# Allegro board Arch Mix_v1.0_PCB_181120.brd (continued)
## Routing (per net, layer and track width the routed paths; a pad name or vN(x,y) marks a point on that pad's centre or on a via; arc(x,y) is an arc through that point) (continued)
VDD_USB_3V: length 9.3
  TOP w0.254: U8.K8 v1(40.37,19.72)
  GND05 w0.305: v1(40.37,19.72) 41.72,19.72 42.38,20.37 42.7,20.37
  GND05 w0.381: 42.7,20.37 43.84,20.37 45.76,22.29 v2(46.37,22.29)
  BOTTOM w0.203: v1(40.37,19.72) 40.37,19.62 40.89,19.1 C59.1
  BOTTOM w0.305: C48.1 v2(46.37,22.29)
VDDA_1V1_CAP: length 2
  TOP w0.254: v1(42.34,16.36) 42.34,16.45 U8.P10
  BOTTOM w0.305: v1(42.34,16.36) 42.7,16.01 C52.1 42.7,15.12 C53.1
VDDA_2V5_CAP: length 2
  TOP w0.254: U8.P8 v1(41.02,16.47)
  BOTTOM w0.305: v1(41.02,16.47) 41.07,16.42 C61.1 C62.1
VDDA_ADC_3V3: length 5.7
  TOP w0.203: 45.01,17.1 44.66,17.44 U8.N14
  TOP w0.305: 45.01,17.1 45.16,16.94 47.22,16.94 C30.1 C29.1 C28.1 R30.2
BOOT_MODE[0]: length 17.1
  TOP w0.127: SW1.4 41.17,29.34 v2(40.44,30.08) 40.34,30.18 39.7,30.18 R19.2 ; U8.F11 v1(42.97,22.32)
  LYR03 w0.127: v2(40.44,30.08) 39.87,29.5 39.87,29.15 41.33,27.69 41.96,27.69 42.99,28.72 44.23,28.72 v2(44.65,29.14)
  BOTTOM w0.102: v1(42.97,22.32) 43.3,22.64 43.3,23.45 43.3,25.39 43.99,26.09 43.99,26.35
  BOTTOM w0.127: v2(44.65,29.14) 44.65,28.7 43.99,28.04 43.99,26.35
BOOT_MODE[1]: length 23.8
  TOP w0.127: v2(46.17,21.22) 46.05,21.34 U8.G14 ; SW1.3 40.66,30.61 v2(40.45,30.81) 40.1,31.17 R18.2
  LYR03 w0.127: v2(48.39,27.66) 47.6,28.45 43.21,28.45 42.16,27.41 41.2,27.41 39.57,29.03 39.57,29.95 40.44,30.81 v2(40.45,30.81)
  BOTTOM w0.127: v2(46.17,21.22) 46.46,21.5 47.43,21.5 47.9,21.97 47.9,27.18 v2(48.39,27.66)
CAN2_RX: length 29.9
  TOP w0.127: U8.L10 v1(42.32,18.42)
  BOTTOM w0.102: v1(42.32,18.42) 42.65,18.74 42.65,19.97 43.31,20.63 46.09,20.63
  BOTTOM w0.127: 46.09,20.63 47.27,20.63 47.55,20.35 48.06,20.35 48.59,20.88 48.59,26.91 49.06,27.38 49.06,27.94 48.64,28.36 48.64,34.39 47.62,35.41 45.03,35.41 42.89,37.55 J3.15
CAN2_TX: length 26.7
  TOP w0.127: v2(47.12,21.08) 47.12,20.96 46.66,20.5 45.87,20.5 45.68,20.69 U8.H14
  BOTTOM w0.127: J3.14 40.35,37.55 42.8,35.1 47.42,35.1 48.39,34.14 48.39,28.25 48.81,27.84 48.81,27.49 48.23,26.92 48.23,21.87 47.45,21.08 v2(47.12,21.08)
DBG_RESET: length 6.6
  TOP w0.305: R51.2 v2(55.29,5.06)
  BOTTOM w0.305: v2(55.29,5.06) 54.73,4.5 52.78,4.5 50.51,2.23 J4.18
DBG_SWD_3V3: length 3.9
  TOP w0.381: D5.2 60.07,2.82 J4.22
DBG_SWD_CLK: length 4.2
  TOP w0.127: J4.19 53.05,3.77 51.44,5.38 R43.2
DBG_SWD_DIO: length 5.2
  TOP w0.127: J4.20 55.19,2.22 52.22,5.19 R44.2
DBG_UART1_3V3: length 3.7
  TOP w0.381: J3.22 60.67,35.07 60.01,34.41 D6.2
DBG_UART1_RXD: length 6.6
  BOTTOM w0.127: J3.19 54.08,36.75 R70.1 54.08,34.57 53.19,33.68 53.19,32.92 53.32,32.79 U10.2
DBG_UART1_TXD: length 6.6
  BOTTOM w0.127: J3.20 55.59,33.06 54.82,32.29 U10.3
DCDC_3V3: length 115.3
  TOP w0.203: U8.E9 U8.F10 v1(42.32,22.32)
  TOP w0.254: R2.1 2.74,23.6 5.98,26.84 7.09,26.84 7.27,26.66 R6.1 ; U8.F5 v1(39.07,22.32) U8.E6 v1(39.07,22.97) ; U8.J10 v1(42.32,19.72)
  TOP w0.305: v2(8.29,25.63) 8.28,25.63 7.97,25.93 R7.1 R6.1 ; C32.1 48.63,19.76 v2(48.61,19.79) R30.1 ; R49.1 v2(54.54,5.13) ; C31.1 v2(47.85,20.8) ; R39.1 R40.1 R41.1 R42.1 ; U5.5 19.18,10.03 v2(19.3,9.91) 20.27,9.91 20.58,10.21 R10.1
  TOP w0.381: LED1.1 3.28,15.71 3.28,15.37 4.68,13.96 v2(5.7,13.96) ; LED2.2 55.72,23.41 55.82,23.51 v2(55.84,23.51) ; v2(54.05,24.39) 54.05,24.46 54.3,24.71 C37.1 ; v2(42.27,8.84) 41.15,8.84 40.89,8.59 R21.1 ; v2(57.76,35.56) 57.54,35.34 D6.1 ; R46.1 53.27,33.1 R45.1 53.27,31.63 53.11,31.47 v2(53.11,31.04) ; D5.1 v2(57.67,6.61) ; R39.1 v2(51.31,33.91) ; R50.1 55.62,33.12 R52.1 55.65,33.66 v2(55.14,34.16) 55.13,34.15
  TOP w0.508: 7.26,36.32 7.33,36.39 J3.1 6.03,37.78 5.92,37.67
  PWR04 w0.102: 38.73,23.29 38.83,23.29 ; 38.73,23.29 37.64,23.29 37.64,23.29 37.16,23.29 ; 38.73,23.29 38.75,23.31 38.75,24.76 ; 36.7,23.93 36.72,23.94 38.52,23.94 ; 40.06,23.93 40.04,23.94 38.94,23.94 38.94,23.94 38.52,23.94 ; 42.67,24.59 41.37,24.59 41.35,24.61 ; 38.56,23.94 38.52,23.94 ; 44.63,23.47 44.6,23.44 44.6,22.61 44.6,22.61 ; 43.43,22 43.43,21.99 42.55,21.99 42.53,22.02 ; 42.52,22.66 42.54,22.64 43.3,22.64 ; 43.3,22.64 43.31,22.63 ; 43.3,22.64 43.3,24.76 43.36,24.82 ; 43.3,22.64 43.48,22.64 43.51,22.61 ; 38.1,23.12 38.1,23.48 38.1,23.48 38.1,23.75 38.1,23.75 38.1,24.13 38.1,24.13 38.1,24.4 38.1,24.4 38.1,24.64 ; 37.47,23.17 37.45,23.18 37.45,24.75 ; 45.24,23.29 40.89,23.29 40.89,23.29 40.72,23.29 ; 40.26,23.29 39.86,23.29 39.86,23.29 39.59,23.29 39.59,23.29 39.5,23.29 ; 43.94,22.58 43.95,22.59 43.95,24.63 43.94,24.64 ; 42.75,25.25 42.65,25.15 42.65,24.78 42.65,24.78 42.65,24.4 42.65,24.4 42.65,22.58 ; 42.65,22.02 42.65,21.8 42.65,21.8 42.65,20.6 ; 38.29,24.59 38.29,24.59 38.56,24.59 38.56,24.59 38.94,24.59 38.94,24.59 39.21,24.59 39.21,24.59 39.55,24.59 ; 42.06,22.61 42,22.67 42,25.26 42.01,25.27 ; 44.63,23.95 44.62,23.94 40.68,23.94 40.67,23.95 ; 43.26,22.02 43.3,21.98 43.3,20.63 ; 39.4,24.74 39.4,23.19
  PWR04 w0.381: v1(39.07,22.32) v1(39.07,22.97)
  BOTTOM w0.102: v1(39.07,22.97) 39.4,23.29 39.86,23.29 39.86,23.29 C64.1
  BOTTOM w0.254: 52.07,33.3 52.07,33.61 51.75,33.29 ; 52.07,33.3 52.06,33.29 51.75,33.29 ; 52.07,33.3 52.07,33.04 51.82,32.79 U10.7 ; U10.8 51.75,33.29
  BOTTOM w0.305: v2(8.29,25.63) 8.16,25.49 R133.1 R134.1 ; R72.1 v2(47.09,15.52) ; R86.1 42.27,32.92 41.73,32.92 ; R86.1 R82.1 R79.1 R77.1 R75.1 R73.1 ; R86.1 42.25,32.96 ; U12.1 22.44,6.39 21.69,5.64 19,5.64 ; R97.1 v2(36.14,33.51) ; 41.73,32.92 41.73,29.42 42.04,29.11 R85.1 R81.1 ; 41.73,32.92 R89.1 R93.1 v2(38.2,32.92) ; C56.1 41.87,22.77 v1(42.32,22.32) ; C47.1 v2(47.42,26.27)
  BOTTOM w0.381: 59.69,35.16 59.41,34.88 C45.1 59.39,34.25 v2(58.95,33.81) 58.8,33.66 58.14,33.66 Q1.2 ; 59.69,35.16 59.69,35.12 60.07,34.74 FB5.1 ; 59.69,35.16 59.74,35.16 v2(59.84,35.26) ; 52.07,33.61 52.07,34.63 C46.1 v2(52.37,35.54) ; v2(11.25,23.58) 11.24,23.58 11.24,23.59 11.49,23.83 FB6.1 v3(11.49,25.14)
  BOTTOM w0.508: 6.6,3.96 6.6,3.07 7.33,2.35 J4.1 7.45,2.22 7.95,2.72 7.95,3.7
  vias: v2(5.96,33.76) v2(6.57,33.86) v2(13.16,6.09) v2(13.54,6.61) v2(13.67,6.1) v2(16.31,6.2) v2(16.28,5.67) v2(16.87,6.2) v2(16.87,5.69) v2(17.45,6.2) v2(17.48,5.69) v2(55.6,28.98) v2(56.11,28.98)
DCDC_OUT:
  vias: v2(30.3,14) v2(30.27,13.54) v2(30.86,13.97) v2(30.96,13.51) v2(31.54,14.04) v2(31.66,13.53)
ENET_CRS_DV: length 45.1
  TOP w0.127: U8.C12 v1(43.62,24.27)
  BOTTOM w0.102: v1(43.62,24.27) 44.09,23.8 45.52,23.8 45.67,23.96 45.68,23.96 45.87,24.15 45.87,24.15 46.09,24.37
  BOTTOM w0.127: J3.5 19.89,35.38 26.67,35.38 27.28,34.77 40.31,34.77 40.97,34.11 47.12,34.11 47.62,33.61 47.62,29.29 46.35,28.02 46.35,24.64 46.09,24.37
ENET_MDC: length 25.6
  TOP w0.127: U8.A7 40.11,25.3 40.11,25.68 40.2,25.77 40.2,27.17 40.28,27.26 40.28,28.86 39.93,29.21 39.04,29.21 38.46,29.8 38.46,30.46 34.16,34.75 25.37,34.75 22.57,37.55 J3.7
ENET_MDIO: length 32.2
  TOP w0.127: v2(21.07,34.23) 21.07,36.74 J3.6 ; U8.C7 v1(39.72,24.27)
  BOTTOM w0.102: v1(39.72,24.27) 39.72,24.74 39.4,25.07 39.4,25.53 39.17,25.76 39.17,26.35
  BOTTOM w0.127: v2(21.07,34.23) 26.23,34.23 26.53,33.93 37.15,33.93 37.52,33.55 37.52,30.51 38.71,29.31 38.92,29.31 39.04,29.31 39.93,28.42 39.93,27.56 39.17,26.8 39.17,26.35
ENET_RXD0: length 36.7
  TOP w0.127: U8.E12 v1(43.62,22.97)
  BOTTOM w0.102: 46.09,23.54 45.87,23.32 43.92,23.32 43.62,23.03 v1(43.62,22.97)
  BOTTOM w0.127: 46.09,23.54 46.96,24.41 46.96,27.64 48.13,28.81 48.13,33.99 47.42,34.7 41.27,34.7 40.64,35.33 29.87,35.33 27.65,37.55 J3.9
ENET_RXD1: length 38.2
  TOP w0.127: U8.D12 v1(43.62,23.62)
  BOTTOM w0.102: v1(43.62,23.62) 43.64,23.6 45.75,23.6 46.09,23.94
  BOTTOM w0.127: J3.8 25.11,37.55 27.61,35.05 40.49,35.05 41.15,34.39 47.27,34.39 47.88,33.78 47.88,29.05 46.66,27.83 46.66,24.51 46.09,23.94
ENET_RXER: length 46
  TOP w0.127: U8.C13 v1(44.27,24.27)
  BOTTOM w0.102: 46.06,26.35 46.06,24.86 45.77,24.56 44.57,24.56 v1(44.27,24.27)
  BOTTOM w0.127: J3.4 14.95,37.55 17.45,35.05 26.47,35.05 27.03,34.49 40.11,34.49 40.79,33.81 47.02,33.81 47.37,33.45 47.37,29.47 46.06,28.16 46.06,26.35
ENET_TX_CLK: length 23.4
  TOP w0.127: U8.B13 44.27,24.91 44.27,25.39 44.55,25.68 45.75,25.68 48.36,28.3 48.36,32.59 45.67,35.28 40.08,35.28 37.81,37.55 J3.13
ENET_TXD0: length 27.1
  TOP w0.127: J3.11 32.73,37.55 35.73,34.55 45.16,34.55 47.42,32.28 47.42,28.37 45.49,26.44 44.39,26.44 43.62,25.67 43.62,24.91 U8.B12
ENET_TXD1: length 28.4
  TOP w0.127: U8.A12 43.3,25.91 44.21,26.82 45.42,26.82 47.02,28.42 47.02,32.08 44.91,34.19 35.41,34.19 34.37,35.23 32.51,35.23 30.19,37.55 J3.10
ENET_TXEN: length 24.5
  TOP w0.127: J3.12 35.27,37.55 37.92,34.9 45.42,34.9 47.93,32.39 47.93,28.42 45.61,26.11 44.48,26.11 44.42,26.04 44.41,26.04 43.95,25.59 U8.A13
FLASH_RST: length 40.3
  TOP w0.102: U8.C14 44.82,24.16 v1(45.09,24.16)
  LYR03 w0.102: 46.09,24.16 v1(45.09,24.16)
  LYR03 w0.127: v2(53.31,11.25) 52.48,10.42 42.75,10.42 39.92,7.58 36.13,7.58 35.97,7.42 v1(35.97,7.39) ; v2(54.11,20.58) 54.11,20.78 52.12,22.76 47.85,22.76 46.46,24.16 46.09,24.16
  BOTTOM w0.127: v1(35.97,7.39) 35.94,7.39 35.61,7.72 R101.1 ; v2(53.31,11.25) 53.72,11.66 53.72,15.34 54.13,15.75 54.13,20.24 54.11,20.26 v2(54.11,20.58)
FLASH_VCC: length 25.4
  TOP w0.254: U8.K5 v1(38.42,19.07)
  TOP w0.305: v2(29.39,12.85) 29.46,12.78 29.67,12.78 30.31,12.14 U7.D1 ; v3(32.92,8.66) 32.45,9.14 U7.B4 ; C18.1 25.73,7.06 v2(25.85,6.94) ; U7.E4 29.23,9.14 v1(29.08,8.99) ; v2(25.4,10.85) 25.43,10.85 25.73,10.54 C17.1
  TOP w0.381: v2(44.37,6.82) 44.35,6.82 44.35,6.86 44.07,7.14 R23.1
  PWR04 w0.102: 37.59,18.74 37.45,18.6 37.45,18.17 37.44,18.16 ; 37.59,18.74 36.93,18.74 36.8,18.61 36.8,18.04 ; 37.59,18.74 37.91,18.74 37.93,18.72 38,18.72 ; 38.75,17.44 38.75,16.98 38.51,16.74 38.38,16.74 ; 38.75,17.44 38.75,18.11 ; 38.75,17.44 38.75,17.44 38.01,17.44 38,17.43 ; 38.1,18.21 38.1,18.28 38.1,18.28 38.1,18.55 38.1,18.55 38.1,18.59 ; 38.75,18.11 38.73,18.09 37.98,18.09 37.97,18.09 ; 38.75,18.11 38.75,18.55 38.73,18.56 38.73,18.75 v1(38.42,19.07)
  BOTTOM w0.203: 25.17,11.31 25.25,11.31
  BOTTOM w0.305: v1(29.08,8.99) 29.01,8.92 C85.1
  BOTTOM w0.381: v2(32.94,6.86) 32.94,6.78 33.6,6.12 35.18,6.12 35.61,6.56 R102.1 ; U11.8 39.33,10.47 C70.1 C73.1 35.66,10.47 R99.1 v2(35.64,9.68) R100.1 35.66,8.64 R95.1 ; R109.1 30.83,11.92 29.9,12.85 v2(29.39,12.85) ; v2(25.4,10.85) 25.4,10.9 25.25,11.05 R118.2
  vias: v2(25.68,6.35) v2(28.84,12.87)
FLEXSPI_CLK: length 16.4
  TOP w0.127: U8.L4 v1(37.77,18.42)
  BOTTOM w0.127: v1(37.77,18.42) 37.45,18.09 37.45,16.65 37.01,16.21 37.01,15.22 36.6,14.81 35.66,14.81 35.56,14.71 35.56,14.48 35.69,14.35 36.73,14.35 36.83,14.25 36.83,14.02 36.73,13.92 35.43,13.92 35.36,13.84 35.36,13.57 35.46,13.46 36.73,13.46 36.83,13.36 36.83,13.08 36.73,12.98 35,12.98 34.92,12.9 34.92,12.6 35.03,12.5 35.76,12.5 35.94,12.32 35.94,11.94 35.65,11.65 R98.1 35.66,11.51 R96.1
FLEXSPI_CLK_B: length 17.3
  TOP w0.127: U8.P2 36.8,16.25 36.53,15.98 36.14,15.98 36.04,15.88 36.04,15.67 36.04,15.57 36.14,15.47 36.53,15.47 36.63,15.37 36.63,15.14 36.55,15.06 35.72,15.06 35.61,14.95 35.61,14.76 35.69,14.68 36.55,14.68 36.63,14.61 36.63,14.38 36.55,14.3 34.96,14.3 34.82,14.17 34.82,14 34.92,13.9 35.76,13.9 35.86,13.79 35.86,13.55 35.78,13.46 35.43,13.46 35.36,13.39 35.36,13.04 35.25,12.93 35.08,12.93 35,13.01 35,13.39 34.93,13.46 34.69,13.46 34.62,13.39 34.62,12.63 34.54,12.55 34.34,12.55 34.24,12.65 34.24,13.21 34.16,13.29 33.94,13.29 33.94,13.28 33.83,13.17 33.83,11.89 33.76,11.81 33.57,11.81 33.47,11.91 33.47,12.42 33.37,12.52 33.19,12.52 33.06,12.4 33.06,11.91 32.96,11.81 32.54,11.81 32.42,11.93 U7.B1
FLEXSPI_D0_A: length 15.4
  TOP w0.127: v1(35.56,12.12) 35.56,12.22 37.24,13.9 37.24,16 37.45,16.22 U8.P3
  LYR03 w0.102: 27.61,10.72 v1(27.58,10.72)
  LYR03 w0.127: v1(27.58,10.72) 27.86,11 29.41,11 29.45,10.96 29.47,10.96 29.66,10.76 29.66,10.74 29.81,10.6 29.81,10.58 30.01,10.38 30.03,10.38 30.04,10.36 32.02,10.36 33.37,11.71 35.15,11.71 v1(35.56,12.12)
  BOTTOM w0.127: R113.1 v1(27.58,10.72) 27.56,10.75 R114.2
FLEXSPI_D0_B: length 17.7
  TOP w0.127: U8.M4 37.78,17.77 37.33,17.77 37.13,17.57 37.13,17.26 36.98,17.11 36.67,17.11 36.48,16.92 36.48,16.7 35.66,15.88 35.66,15.85 35.65,15.83 35.65,15.53 33.56,13.45 33.56,13.44 33.2,13.07 33.19,13.07 32.94,12.83 32.11,12.83 31.9,12.63 31.9,11.91 31.72,11.74 30.96,11.74 30.76,11.53 30.76,9.98 30.92,9.82 31.27,9.82 31.37,9.72 31.37,9.53 31.29,9.45 30.94,9.45 30.76,9.27 30.76,8.99 30.58,8.82 30.57,8.82 30.56,8.81 29.94,8.81 29.77,8.64 29.77,7.67 29.9,7.55 30.23,7.55 30.42,7.74 U7.D5
FLEXSPI_D1_A: length 16.2
  TOP w0.127: v1(36.37,12.47) 36.45,12.47 37.47,13.49 37.47,15.83 37.77,16.13 37.77,17.12 38.09,17.44 U8.N4
  LYR03 w0.127: v1(27.58,11.53) 29.2,11.53 29.28,11.45 29.29,11.45 29.55,11.19 29.56,11.19 29.62,11.13 32.38,11.13 33.73,12.47 v1(36.37,12.47)
  BOTTOM w0.127: R112.1 27.69,11.64 v1(27.58,11.53) 27.48,11.63 R116.2
FLEXSPI_D1_B: length 17.5
  TOP w0.127: U8.M3 37.24,18.09 36.88,17.73 36.68,17.73 36.68,17.73 36.27,17.73 36.27,17.73 36.03,17.73 36.03,17.73 35.81,17.73 35.31,17.23 35.31,15.52 33.33,13.55 33.33,13.53 33.1,13.3 33.09,13.3 32.89,13.11 29.82,13.11 29.57,13.36 28.75,13.36 28.35,12.96 28.35,12.47 28.5,12.32 28.91,12.32 29.01,12.22 29.01,11.96 28.91,11.86 28.45,11.86 28.35,11.76 28.35,10.11 28.47,9.98 29.27,9.98 U7.E3
FLEXSPI_D2_A: length 17.6
  TOP w0.127: U8.P4 38.13,16.76 38.13,16.03 37.69,15.6 37.69,12.73 37.3,12.33 37.3,12.33 37.1,12.13 37.1,12.13 36.73,11.76 35.56,11.76 35.1,11.3 35.1,7.19 34.26,6.35 31.92,6.35 v1(31.41,6.86)
  BOTTOM w0.127: R106.2 31.65,7.29 R108.1 v1(31.41,6.86)
FLEXSPI_D2_B: length 18.3
  TOP w0.127: v1(29.33,10.62) 29.42,10.72 U7.E2 ; U8.M5 v1(38.42,17.77)
  LYR03 w0.127: v1(29.33,10.62) 29.33,10.58 29.77,10.14 32.12,10.14 32.84,10.85 32.85,10.85 32.85,10.85 33.13,10.85 33.14,10.85 33.37,10.85 33.48,10.95 33.48,11.36 33.58,11.46 33.78,11.46 33.88,11.36 33.88,10.95 33.98,10.85 34.19,10.85 34.29,10.95 34.29,11.36 34.39,11.46 34.59,11.46 34.69,11.36 34.69,10.95 34.8,10.85 35.11,10.85 36.37,12.12 37.58,12.12 v1(37.62,12.16)
  BOTTOM w0.127: v1(37.62,12.16) 37.59,12.16 37.59,12.19 37.87,12.47 37.87,16.18 38.02,16.33 38.02,17.37 v1(38.42,17.77)
FLEXSPI_D3_A: length 17.5
  TOP w0.127: U8.P5 38.75,16.75 38.43,16.44 38.43,15.93 37.95,15.44 37.95,12.98 v1(38.3,12.63)
  LYR03 w0.127: v1(38.3,12.63) 38.3,12.3 37.8,11.79 36.45,11.79 34.5,9.84 v1(27.59,9.84)
  BOTTOM w0.127: R111.1 v1(27.59,9.84) 27.58,9.83 R115.2
FLEXSPI_D3_B: length 17.6
  TOP w0.127: U7.E1 v1(29.42,11.79) ; U8.L5 v1(38.42,18.42)
  LYR03 w0.127: v1(29.42,11.79) 29.42,11.7 29.74,11.38 30.58,11.38 30.66,11.46 30.66,11.81 30.76,11.91 30.96,11.91 31.06,11.81 31.06,11.46 31.14,11.38 31.39,11.38 31.47,11.46 31.47,11.81 31.57,11.91 31.77,11.91 31.87,11.81 31.87,11.46 31.95,11.38 32.21,11.38 33.66,12.83 36.6,12.83 v1(36.96,12.47)
  BOTTOM w0.127: v1(36.96,12.47) 37.49,13.01 37.49,16.23 37.74,16.49 37.74,17.74 v1(38.42,18.42)
FLEXSPI_DQS: length 16.5
  TOP w0.127: v1(33.41,7.39) 33.41,7.39 33.73,7.07 33.92,7.07 33.93,7.06 34.47,7.06 34.76,7.35 34.76,11.9 37.01,14.15 37.01,16.1 37.12,16.21 37.12,16.91 37.45,17.24 U8.N3
  LYR03 w0.127: v1(33.41,7.39) 33.38,7.39 33.27,7.49 31.17,7.49 v1(30.5,6.83)
  BOTTOM w0.127: R110.1 v1(30.5,6.83)
FLEXSPI_SS0: length 14.1
  TOP w0.127: U8.L3 v1(37.12,18.42)
  BOTTOM w0.127: R109.2 31.6,11.81 32.05,12.26 R105.1 32.78,12.27 R104.1 33.73,12.65 33.5,12.88 32.41,12.88 32.31,12.98 32.31,13.18 32.44,13.31 32.77,13.31 32.78,13.3 33.1,13.3 33.11,13.31 34.65,13.31 34.95,13.62 34.95,14.89 35.28,15.22 36.32,15.22 36.55,15.44 36.55,16.21 37.12,16.78 v1(37.12,18.42)
GPIO_AD_B1_04: length 43.3
  TOP w0.127: U8.L12 v1(43.62,18.42)
  LYR03 w0.102: 43.3,15.68 43.28,15.7 43.28,17.61 43.3,17.63 43.3,17.9 43.28,17.92 43.28,18.07 v1(43.62,18.42)
  LYR03 w0.127: 43.3,15.68 43.3,15.08 v2(43.74,14.63)
  BOTTOM w0.127: v2(43.74,14.63) 43.76,14.61 43.76,14.61 44.73,13.64 44.73,12.69 44.7,12.67 44.7,12.07 43.64,11 42.09,11 40.73,9.64 40.73,6.49 39.75,5.51 33.76,5.51 33.1,4.85 20.14,4.85 18.92,3.63 16.36,3.63 J4.4
GPIO_AD_B1_05: length 44.9
  TOP w0.127: U8.K12 v1(43.62,19.07)
  LYR03 w0.102: 45.72,16.31 44.63,17.4 44.63,18.06 v1(43.62,19.07)
  LYR03 w0.127: 45.72,16.31 46.94,16.31 v2(47.8,15.44)
  BOTTOM w0.127: J4.5 17.5,2.23 17.93,2.23 20.32,4.62 33.22,4.62 33.86,5.26 40.56,5.26 40.65,5.35 40.65,5.35 41.27,5.97 41.53,6.23 41.53,10.03 42.27,10.77 43.79,10.77 44.93,11.91 44.93,12.57 v2(47.8,15.44)
GPIO_AD_B1_06: length 44.3
  TOP w0.127: U8.J12 v1(43.62,19.72)
  LYR03 w0.102: 46.18,16.69 45.85,16.69 44.96,17.58 44.96,19.1 44.34,19.72 v1(43.62,19.72)
  LYR03 w0.127: 46.18,16.69 47.24,16.69 48.29,15.65 48.29,15.19 47.83,14.73 47.83,14.74 47.78,14.74 47.78,14.73 v2(47.78,14.73)
  BOTTOM w0.127: v2(47.78,14.73) 45.19,12.14 45.19,11.79 43.99,10.59 43.97,10.59 43.92,10.54 43.78,10.54 42.39,10.54 41.76,9.91 41.76,6.02 40.74,5.01 34.05,5.01 34.02,4.98 33.96,4.98 33.32,4.34 22.15,4.34 J4.6
GPIO_AD_B1_07: length 45.4
  TOP w0.127: U8.K10 v1(42.32,19.07)
  LYR03 w0.102: v1(42.32,19.07) 42.65,18.74 42.65,17.4 42.72,17.32 42.72,16.08 42.52,15.88 42.52,15.68
  LYR03 w0.127: 42.52,15.68 42.52,13.51 43.28,12.75 47.13,12.75 v2(47.92,13.54)
  BOTTOM w0.127: v2(47.92,13.54) 47.98,13.48 47.98,10.14 47.7,9.86 44.37,9.86 42.6,8.08 42.6,6.67 42.58,6.65 42.58,6.39 40.97,4.78 34.14,4.78 33.48,4.12 28.9,4.12 28.87,4.09 27.43,4.09 26.59,3.25 23.6,3.25 J4.7
GPIO_AD_B1_08: length 41.1
  TOP w0.102: 46.42,19.58 46.36,19.58 45.57,20.37 44.27,20.37 U8.H13
  TOP w0.127: 46.42,19.58 v2(46.56,19.58)
  LYR03 w0.127: v2(48.49,14.71) 48.69,14.91 48.69,15.72 47.62,16.79 47.62,18.52 v2(46.56,19.58)
  BOTTOM w0.127: J4.8 25.88,2.22 27.5,3.84 28.94,3.84 28.99,3.89 33.58,3.89 34.24,4.55 41.17,4.55 42.81,6.19 42.81,6.56 42.82,6.57 42.82,7.95 44.5,9.63 47.83,9.63 48.49,10.29 v2(48.49,14.71)
HF_CLK: length 3.4
  TOP w0.127: v1(34.4,12.09) 34.39,12.09 34.39,12.07 34.38,12.06 34.38,11.72 34.16,11.51 32.79,11.51 U7.B2
  BOTTOM w0.127: R98.2 34.88,11.6 v1(34.4,12.09)
HF_D0_A: length 2.3
  TOP w0.127: U7.D3 30.42,10.33 30.19,10.56 30.19,10.68 v1(30.15,10.72)
  BOTTOM w0.127: v1(30.15,10.72) 30.12,10.72 29.87,10.97 29.01,10.97 R113.2
HF_D1_A: length 2.5
  TOP w0.127: U7.D2 30.34,11.14 30.12,11.35 30.12,11.75 v1(30.12,11.75)
  BOTTOM w0.127: v1(30.12,11.75) 30.12,11.75 30.12,11.63 29.9,11.41 28.98,11.41 28.76,11.63 R112.2
HF_D2_A: length 1.5
  TOP w0.127: v1(30.96,8.64) 31.42,9.09 U7.C4
  BOTTOM w0.127: v1(30.96,8.64) 31.41,8.19 R108.2
HF_D3_A: length 2
  TOP w0.127: v1(29.87,9.42) 29.87,9.35 30.1,9.12 30.4,9.12 U7.D4
  BOTTOM w0.127: v1(29.87,9.42) 29.46,9.84 R111.2
HF_DQS: length 3.3
  TOP w0.127: U7.C3 31.5,10.14 31.9,9.73 v1(31.9,9.42)
  BOTTOM w0.127: R110.2 30.5,8.68 31.24,9.42 v1(31.9,9.42)
HF_RST: length 2.6
  TOP w0.127: v1(34.26,8.66) 33.79,9.14 U7.A4
  BOTTOM w0.127: R101.2 34.85,8.64 R100.2 v1(34.26,8.66)
HF_SS0: length 3.3
  TOP w0.127: v1(31.93,10.75) 31.72,10.54 31.14,10.54 31.04,10.64 31.04,10.97 31.2,11.14 U7.C2
  BOTTOM w0.127: R105.2 32.77,10.98 32.54,10.75 v1(31.93,10.75)
I2C1_SCL: length 52.6
  TOP w0.127: U8.J11 v1(42.97,19.72) ; J5.42 61.41,28.21 61.34,28.14 52.93,28.14 52.48,28.6 52.48,29.82 53.8,31.14 53.8,32.82 R50.2 54.1,33.56 52.86,34.8 48.41,34.8 J3.16
  BOTTOM w0.102: v1(42.97,19.72) 43.55,20.3 46.09,20.3
  BOTTOM w0.127: J3.16 45.58,37.78 48.88,34.47 48.88,28.51 49.58,27.81 49.58,20.73 49.25,20.4 48.54,20.4 48.16,20.02 47.35,20.02 47.07,20.3 46.09,20.3
I2C1_SDA: length 55.1
  TOP w0.127: U8.K11 v1(42.97,19.07) ; J3.17 47.97,35.7 48.54,35.13 54.84,35.13 56.42,33.55 R52.2 56.42,33.02 56.12,32.73 55.93,32.73 55.9,32.7 54.27,32.7 54.05,32.49 54.05,31.07 52.76,29.78 52.76,28.78 53.09,28.45 61.19,28.45 61.45,28.71 J5.43
  BOTTOM w0.102: 46.09,20 44.51,20 43.9,19.39 43.29,19.39 42.97,19.07 v1(42.97,19.07) ; 49.15,31.19 49.15,29.69
  BOTTOM w0.127: 46.09,20 46.84,20 47.48,19.37 48.83,19.37 49.86,20.4 49.86,27.94 49.15,28.65 49.15,29.69 ; J3.17 47.97,35.95 49.15,34.77 49.15,31.19
LCD_BL_PWM: length 112.4
  TOP w0.127: R4.1 2.74,21.11 2.9,20.96 6.63,20.96 6.8,20.78 v2(6.86,20.78) ; R55.1 62.3,34.15 63.6,32.85 63.6,32.84 63.69,32.74 63.7,32.74 64.72,31.73 v2(64.72,28.88) ; v1(42.97,17.77) U8.M11
  LYR03 w0.102: v1(42.97,17.77) 42.97,15.68
  LYR03 w0.127: 49.1,13.97 49.23,13.97 ; 49.1,13.97 49.25,13.82 ; 49.1,13.97 44.42,13.97 43.97,13.51 43.46,13.51 42.97,14 42.97,15.68 ; 49.23,13.97 49.25,13.94 49.25,13.82 ; 49.23,13.97 49.4,13.97 ; 49.25,13.82 49.4,13.97 ; 49.25,13.82 49.25,13.31 47.93,11.99 42.77,11.99 39.85,9.07 30.63,9.07 30.1,8.54 19.84,8.54 18.86,9.51 16.37,9.51 15.57,8.71 7.93,8.71 7.47,9.17 7.47,13.36 5.77,15.06 5.77,19.69 v2(6.86,20.78) ; 49.4,13.97 49.76,13.97 50.16,14.38 64.33,14.38 66.74,16.79 66.88,16.92 66.88,26.74 65.47,28.14 65.46,28.14 v2(64.72,28.88)
LCD_CLK: length 11.4
  TOP w0.127: J5.32 61.5,23.21 v2(61,23.71) ; v2(56.41,24.72) 56.41,25.78 55.37,26.82 54.48,26.82 54.25,26.6 C36.1 54.23,26.26 R47.2
  LYR03 w0.127: v2(61,23.71) 60.05,24.66 56.49,24.66 56.44,24.72 v2(56.41,24.72)
LCD_PWREN: length 39.4
  TOP w0.127: U8.L7 v1(39.72,18.42)
  LYR03 w0.102: v1(39.72,18.42) 39.4,18.09 38.86,18.09 38.75,18.2 38.75,20.54 38.9,20.69 40.4,20.69 42.52,20.69 42.65,20.82 42.65,21.19 42.8,21.34 43.2,21.34 43.3,21.44 43.3,21.94 43.95,22.59 43.95,23.17 44.58,23.8 46.09,23.8
  LYR03 w0.127: 46.09,23.8 46.43,23.8 47.8,22.43 51.79,22.43 v2(52.78,21.44)
  BOTTOM w0.127: v2(52.78,21.44) 52.73,21.49 52.12,21.49 50.97,22.65 50.97,29.78 51.56,30.38 53.7,30.38 55.5,32.18 55.5,32.41 56.34,33.25 Q1.1 56.34,34.69 R67.1
LCDIF_CLK: length 20
  TOP w0.127: U8.D7 v1(39.72,23.62) ; R47.1 52.62,26.25 52.62,25.81 52.93,25.5 v2(53.82,25.5)
  LYR03 w0.102: v1(39.72,23.62) 40.11,24 40.11,25.22 41.23,26.35
  LYR03 w0.127: v2(53.82,25.5) 53.75,25.43 50.65,25.43 49.17,26.9 48.46,26.9 47.29,28.07 43.43,28.07 42.34,26.98 41.86,26.98 41.23,26.35
LCDIF_D0: length 61.2
  TOP w0.127: v2(44.01,31.6) 43.03,30.62 43.03,28.58 41.03,26.58 41.03,24.27 U8.C8 ; v2(65.6,26.21) 66.68,25.13 66.68,11.56 64.33,9.21 J5.4
  LYR03 w0.127: v2(44.01,31.6) 44.01,31.59 43.33,30.91 41.96,30.91 41.71,31.17 41.71,32.21 42.21,32.72 47.65,32.72 52.07,28.3 56.52,28.3 57.81,27 64.81,27 v2(65.6,26.21)
  BOTTOM w0.127: R80.2 v2(44.01,31.6) R79.2
LCDIF_D1: length 54.9
  TOP w0.127: J5.5 64.22,9.71 66.35,11.84 66.35,24.66 65.56,25.45 65.56,25.5 v2(65.56,25.5) ; v2(42.27,31.6) 42.32,31.55 42.32,29.16 41.96,28.81 41.38,28.81 40.67,28.09 40.67,27.17 40.45,26.95 40.45,25.62 40.37,25.54 40.37,25.08 40.7,24.75 U8.B8
  LYR03 w0.127: v2(65.56,25.5) 64.34,26.72 57.58,26.72 56.29,28.02 51.87,28.02 47.5,32.39 43.05,32.39 v2(42.27,31.6)
  BOTTOM w0.127: R86.2 42.28,31.61 v2(42.27,31.6) 42.28,31.59 R87.2
LCDIF_D2: length 51.6
  TOP w0.127: J5.6 64.16,10.21 65.99,12.04 65.99,24.39 64.65,25.73 v2(64.67,25.73) ; v2(43.14,31.6) 42.65,31.1 42.65,28.68 40.7,26.74 40.7,26.24 40.7,26.24 U8.A8
  LYR03 w0.127: v2(64.67,25.73) 63.98,26.42 57.38,26.42 56.03,27.76 51.56,27.76 47.29,32.03 43.57,32.03 v2(43.14,31.6)
  BOTTOM w0.127: R82.2 v2(43.14,31.6) R83.2
LCDIF_D3: length 48.1
  TOP w0.127: J5.7 64.05,10.71 65.07,11.73 65.07,22.83 v2(65.56,23.32) ; U8.A9 41.35,26.4 43.41,28.46 43.41,30.08 44.87,31.54 v2(44.87,31.6)
  LYR03 w0.127: v2(65.56,23.32) 63.32,23.32 61.19,25.45 56.82,25.45 55.32,26.95 50.88,26.95 47.07,30.76 45.67,30.76 44.87,31.56 v2(44.87,31.6)
  BOTTOM w0.127: R78.2 v2(44.87,31.6) R77.2
LCDIF_D4: length 48.9
  TOP w0.127: v2(45.73,31.6) 45.99,31.34 45.99,28.85 45.49,28.35 43.81,28.35 41.67,26.2 41.67,24.91 U8.B9 ; v2(65.15,24.39) 65.15,23.65 64.8,23.29 64.8,12.11 63.89,11.21 J5.8
  LYR03 w0.127: v2(65.15,24.39) 64.31,24.39 62.92,25.78 57,25.78 55.55,27.23 51.1,27.23 47.22,31.12 46.22,31.12 v2(45.73,31.6)
  BOTTOM w0.127: R75.2 v2(45.73,31.6) R76.2
LCDIF_D5: length 54.9
  TOP w0.127: v2(64.67,25.02) 64.64,25.02 64.52,24.89 64.52,14.38 63.35,13.21 J5.12 ; U8.C9 v1(41.67,24.27)
  LYR03 w0.127: v2(40.46,31.55) 41.99,33.08 47.77,33.08 52.27,28.58 57.53,28.58 58.8,27.31 65.25,27.31 66.12,26.44 66.12,25.43 65.71,25.02 v2(64.67,25.02)
  BOTTOM w0.102: v1(41.67,24.27) 41.62,24.27 40.89,25 40.89,26.35
  BOTTOM w0.127: 40.89,26.35 40.89,31.17 40.51,31.55 v2(40.46,31.55) 40.39,31.47 R90.2 R89.2 39.75,32.18
LCDIF_D6: length 60.6
  TOP w0.127: v2(64.25,28.37) 64.21,28.33 64.21,25.98 64.22,25.97 64.22,25.64 64.21,25.63 64.21,14.68 63.24,13.71 J5.13 ; 41.33,33.15 SW1.1 R16.2 39.68,33.43 39.37,33.73 v2(39.37,33.76) ; U8.D9 v1(41.67,23.62)
  LYR03 w0.127: v2(64.25,28.37) 63.83,28.37 63.7,28.25 59.33,28.25 57.53,30.05 54.79,30.05 53.99,30.85 53.99,31.89 52.81,33.07 49.3,33.07 48.23,34.14 39.75,34.14 v2(39.37,33.76)
  BOTTOM w0.102: v1(41.67,23.62) 41.51,23.62 40.26,24.86 40.26,26.18 40.3,26.22 40.3,26.35
  BOTTOM w0.127: v2(39.37,33.76) 38.05,33.76 37.77,33.48 37.77,30.61 38.82,29.57 39.17,29.57 40.3,28.44 40.3,26.35
LCDIF_D7: length 42.9
  TOP w0.127: v2(63.83,25.81) 63.93,25.7 63.93,14.96 63.18,14.21 J5.14 ; v2(46.57,31.6) 46.33,31.36 46.33,28.7 45.67,28.04 43.97,28.04 42,26.07 U8.A10
  LYR03 w0.127: v2(63.83,25.81) 63.53,26.11 57.15,26.11 55.78,27.48 51.36,27.48 47.24,31.6 v2(46.57,31.6)
  BOTTOM w0.127: R74.2 v2(46.57,31.6) R73.2
LCDIF_D8: length 47.1
  TOP w0.127: v2(59.56,15.01) 59.87,14.71 J5.15 ; U8.C10 v1(42.32,24.27)
  LYR03 w0.127: v2(41.68,28.35) 43.28,29.95 47.4,29.95 50.67,26.67 55.12,26.67 56.72,25.07 61.04,25.07 63.04,23.06 63.7,23.06 64.62,22.15 64.62,16.84 63.8,16.03 59.84,16.03 59.61,15.8 59.61,15.06 v2(59.56,15.01)
  BOTTOM w0.102: 41.76,26.35 41.76,25 42.32,24.43 v1(42.32,24.27)
  BOTTOM w0.127: v2(41.68,28.35) 42.15,28.35 42.15,28.35 R85.2 42.29,28.23 42.28,28.22 R88.2 41.87,27.65 41.76,27.54 41.76,26.35
LCDIF_D9: length 57.9
  TOP w0.127: SW1.2 40.84,31.88 v2(40.46,32.26) 40.36,32.16 R17.2 ; J5.16 61.18,15.21 v2(60.94,15.45) ; U8.D10 v1(42.32,23.62)
  LYR03 w0.127: v2(60.94,15.45) 64.65,15.45 66.4,17.2 66.4,26.49 65.27,27.61 58.98,27.61 57.18,29.41 54.38,29.41 53.44,30.35 51.03,30.35 47.96,33.43 41.63,33.43 v2(40.46,32.26)
  BOTTOM w0.102: v1(42.32,23.62) 42.32,23.77 42,24.09 42,24.42 41.3,25.12 41.3,26.35
  BOTTOM w0.127: 41.3,26.35 41.2,26.45 41.2,31.52 v2(40.46,32.26)
LCDIF_D10: length 64.6
  TOP w0.127: J5.17 61.23,15.71 61.1,15.84 60.39,15.84 v2(60.15,15.6) ; U8.E10 v1(42.32,22.97)
  LYR03 w0.127: v2(60.15,15.6) 60.71,15.04 64.67,15.04 66.65,17.02 66.65,26.65 65.38,27.92 59.18,27.92 57.38,29.72 54.56,29.72 53.67,30.61 53.67,31.19 52.63,32.23 49.66,32.23 48.11,33.78 40.47,33.78 38.23,31.54 v2(38.23,31.47)
  BOTTOM w0.102: 40.56,26.35 40.56,24.89 41.51,23.94 41.81,23.94 42,23.75 42,23.29 v1(42.32,22.97)
  BOTTOM w0.127: R93.2 R94.2 38.23,31.47 v2(38.23,31.47) 38.23,30.53 38.89,29.87 39.27,29.87 40.56,28.58 40.56,26.35
LCDIF_D11: length 37.2
  TOP w0.127: U8.E11 v1(42.97,22.97) ; J5.22 63.38,18.21 63.48,18.11 v2(63.48,18.11)
  LYR03 w0.127: v2(63.48,18.11) 64.36,19 64.36,21.54 63.96,21.95 63.35,21.95 62.03,23.27 56.87,23.27 53.75,26.39 50.44,26.39 47.27,29.57 44.3,29.57 v2(43.87,29.14)
  BOTTOM w0.102: 43.65,26.35 43.65,26.3 42.67,25.33 42.67,24.51 42.65,24.49 42.65,23.29 v1(42.97,22.97)
  BOTTOM w0.127: 43.65,26.35 43.65,27.52 43.52,27.65 R84.2 43.15,27.66 R81.2 43.58,28.35 43.87,28.63 v2(43.87,29.14)
LCDIF_D12: length 29.4
  TOP w0.127: v2(45.23,27.27) 45.19,27.27 45.19,27.32 44.82,27.69 44.1,27.69 42.65,26.24 U8.A11 ; J5.23 63.39,18.71 v2(63.5,18.82)
  LYR03 w0.127: v2(63.5,18.82) 63.65,18.82 64.01,19.18 64.01,19.79 63.78,20.02 63.3,20.02 61.95,21.36 61.95,22.15 61.32,22.79 54.58,22.79 52.65,24.72 49.61,24.72 47.04,27.28 45.19,27.28 45.19,27.27 v2(45.23,27.27)
LCDIF_D13: length 27.6
  TOP w0.127: v2(44.52,27.27) 44.13,27.27 42.98,26.12 42.98,24.92 U8.B11 ; v2(63.48,19.53) 63.15,19.21 J5.24
  LYR03 w0.127: v2(44.52,27.27) 45.07,26.72 46.33,26.72 47.33,25.72 47.95,25.72 49.26,24.41 52.53,24.41 54.42,22.52 61.23,22.52 61.54,22.2 61.54,21.45 63.46,19.53 v2(63.48,19.53)
LCDIF_D14: length 22.5
  TOP w0.127: U8.C11 v1(42.97,24.27) ; J5.25 61.32,19.71 v2(61.09,19.94)
  LYR03 w0.102: v1(42.97,24.27) 44.01,25.3 45.81,25.3 46.09,25.02
  LYR03 w0.127: 46.09,25.02 47.95,23.17 52.15,23.17 55.38,19.94 v2(61.09,19.94)
LCDIF_D15: length 24
  TOP w0.127: J5.26 61.54,20.21 61.3,20.45 v2(60.55,20.45) ; U8.D11 v1(42.97,23.62)
  LYR03 w0.102: v1(42.97,23.62) 42.96,23.62 42.65,23.93 42.65,24.72 43.56,25.63 46.09,25.63
  LYR03 w0.127: v2(60.55,20.45) 55.3,20.45 52.25,23.5 48.87,23.5 47.41,24.96 46.76,24.96 46.09,25.63
  BOTTOM w0.102: 42.97,23.62 v1(42.97,23.62)
LCDIF_ENABLE: length 30.7
  TOP w0.127: v2(63.45,21.24) 63.42,21.21 J5.28 ; U8.E7 v1(39.72,22.97)
  LYR03 w0.102: 41.36,25.82 40.39,24.84 40.39,23.63 v1(39.72,22.97)
  LYR03 w0.127: v2(63.45,21.24) 61.68,23.01 54.74,23.01 52.7,25.05 49.76,25.05 47.11,27.69 43.59,27.69 42.49,26.6 42.14,26.6 41.36,25.82
LCDIF_HSYNC: length 26.7
  TOP w0.127: v2(60.5,21.41) 61,21.41 61.3,21.71 J5.29 ; U8.E8 v1(41.02,22.97)
  LYR03 w0.102: 46.09,26.32 42.47,26.32 40.67,24.51 40.67,23.32 v1(41.02,22.97)
  LYR03 w0.127: v2(60.5,21.41) 60.43,21.49 55.01,21.49 52.42,24.08 49.12,24.08 47.74,25.47 47.18,25.47 46.33,26.32 46.09,26.32
LCDIF_VSYNC: length 26.5
  TOP w0.127: J5.30 60.89,22.21 v2(60.81,22.12) ; U8.D8 v1(41.02,23.62)
  LYR03 w0.102: 46.09,25.99 42.7,25.99 41.02,24.31 v1(41.02,23.62) 41.03,23.62
  LYR03 w0.127: 46.09,25.99 46.2,25.99 46.98,25.21 47.61,25.21 49.02,23.8 52.37,23.8 55.16,21.02 60.82,21.02 61.09,21.29 61.09,21.85 v2(60.81,22.12)
LDO_1V8: length 2.3
  BOTTOM w0.305: C91.1 22.34,11.9 21.74,12.5 C92.1 R122.1
LDO_3V3: length 39.7
  LYR03 w0.381: v2(16.81,9.09) 16.84,9.07 18.57,9.07 19.49,8.15 32.24,8.15 32.25,8.15 35.88,8.15 35.89,8.17 39.59,8.17 42.75,11.33 47.77,11.33 49.25,12.8 v2(49.3,12.8)
  BOTTOM w0.203: C102.1 15.54,10.67 ; R126.1 15.54,9.76
  BOTTOM w0.33: v2(49.3,12.8) 49.43,12.93 49.43,14.58 47.96,16.05 R71.1
MCU_DCDC_IN_3V3: length 7
  TOP w0.203: U8.L2 v1(36.47,18.42) U8.L1 ; U8.K4 v1(37.77,19.07)
  LYR03 w0.102: 37.43,19.39 36.94,19.39 36.8,19.25 U8.L2 37.43,18.74 37.45,18.73 37.45,18.62 37.45,18.21 37.28,18.04 37.28,18.04
  LYR03 w0.203: v1(36.47,18.42) 36.88,18.01 37.25,18.01 37.28,18.04 ; 37.76,19.07 37.76,19.04 37.45,18.73 ; 37.76,19.07 v1(37.77,19.07) ; 37.76,19.07 37.76,19.07 37.43,19.39
  LYR03 w0.305: v1(36.47,18.42) U8.L2
  BOTTOM w0.305: v1(36.47,18.42) 36.4,18.35 C74.1
MCU_ONOFF: length 21.5
  TOP w0.127: R34.2 49.16,8.13 C34.1 49.17,10.97 v2(49.33,11.13)
  TOP w0.203: U8.M6 v1(39.07,17.77)
  PWR04 w0.102: v1(39.07,17.77) 39.08,17.77 39.43,17.42 39.43,16.87 38.24,15.68
  PWR04 w0.127: v2(49.33,11.13) 49.15,11.13 48.97,11.3 40.72,11.3 37.9,14.12 37.9,15.34 38.24,15.68
PMIC_ON_REQ: length 31.9
  TOP w0.127: v2(26.54,14.73) 26.54,14.63 25.32,13.41 25.32,12.47 24.26,11.41 22.68,11.41 22,10.72 22,9.88 21.44,9.32 21.44,8.13 21.84,7.72 R11.1 R12.1 ; U8.K7 v1(39.72,19.07)
  LYR03 w0.102: 34.28,19.22 37.21,16.28 38.96,16.28 40.05,17.37 40.05,18.74 v1(39.72,19.07)
  LYR03 w0.127: 34.28,19.22 33.83,19.66 29.9,19.66 26.54,16.31 v2(26.54,14.73)
POR_B: length 63.9
  TOP w0.203: U8.M7 v1(39.72,17.77)
  TOP w0.305: R51.1 56.08,5.72 v2(56.08,5.16) ; v2(48.31,7.95) 48.31,7.98 47.83,8.46 R24.2 ; 53.34,29.69 v2(53.26,29.69) 54.7,31.13 R54.1
  TOP w0.33: R36.2 49.63,11.53 v2(49.33,11.84)
  LYR03 w0.305: v2(48.31,7.95) 53.52,7.95 53.59,7.88 v2(53.59,7.92)
  LYR03 w0.33: v2(54.2,13.59) 51.23,13.59 49.53,11.89 49.38,11.89 v2(49.33,11.84)
  PWR04 w0.305: v1(39.72,17.77) 39.82,17.67 39.82,16.7 38.38,15.26 v2(38.38,15.13) 38.42,15.13 38.89,14.66 38.89,13.69 40.36,12.22 48.9,12.22 49.28,11.84 v2(49.33,11.84)
  BOTTOM w0.305: v2(56.08,5.16) 54.25,6.99 54.25,7.65 ; 54.25,8.26 54.25,7.98 ; 54.25,8.26 53.95,7.95 ; 54.25,8.26 54.25,13.59 ; 54.25,7.98 54.23,7.95 53.95,7.95 ; 54.25,7.98 54.25,7.65 ; v2(53.59,7.92) 53.59,7.88 53.67,7.95 53.95,7.95 ; v2(53.26,29.69) 53.34,29.69 54.66,28.37 54.66,13.9 54.36,13.59 54.25,13.59 ; v1(39.72,17.77) 39.65,17.69 39.65,17.22 C66.1 ; 53.95,7.95 54.25,7.65 ; 54.25,13.59 v2(54.2,13.59) ; v2(38.38,15.13) 38.42,15.17 R91.2
POR_BUTTON: length 37.4
  TOP w0.102: v2(45.29,5.13) 46.05,5.13 48.83,7.91 48.83,13.14 49.21,13.53 R35.2 ; 22.86,7.67 23.24,7.29 23.24,6.1 v2(23.44,5.89)
  TOP w0.127: 22.86,7.67 R11.2 22.81,8.62 C15.1 22.83,8.64 22.83,8.99 22.61,9.22 D1.2
  LYR03 w0.127: v2(45.29,5.13) 44.95,4.79 27.85,4.79 27.28,5.36 23.98,5.36 v2(23.44,5.89)
PWR_USB_OTG: length 3.4
  TOP w0.127: 3.02,19.81 2.91,19.93
  TOP w0.381: 2.91,19.93 2.77,20.07 R5.1
  TOP w0.508: 3.02,19.81 3.2,19.64 4.97,19.64 U1.5
QF_CLK: length 26.1
  TOP w0.127: v2(37.34,11.03) 37.34,11.3 37.24,11.41 35.56,11.41 35.46,11.3 35.46,11.08 35.56,10.97 36.68,10.97 36.8,10.85 36.8,10.62 36.73,10.54 35.48,10.54 35.41,10.47 35.41,10.19 35.48,10.11 37.39,10.11 37.57,9.93 37.57,9.45 37.39,9.27 35.61,9.27 35.51,9.17 35.51,8.99 35.61,8.89 37.47,8.89 37.57,8.79 37.57,8.59 37.47,8.49 35.64,8.49 35.53,8.38 35.53,8.18 35.61,8.1 37.41,8.1 37.52,8 37.52,7.85 37.41,7.75 35.74,7.75 35.61,7.62 35.61,6.68 35.76,6.53 37.39,6.53 v2(37.69,6.83)
  BOTTOM w0.102: v2(37.34,11.03) 37.34,11.08
  BOTTOM w0.127: R96.2 37.31,11.05 v2(37.34,11.03) ; U11.6 38.02,7.82 37.69,7.49 v2(37.69,6.83)
QF_D0_A: length 26.1
  LYR03 w0.127: v2(27.58,6.38) 27.84,6.12 28.06,6.12 28.17,6.02 28.17,5.16 28.27,5.06 28.47,5.06 28.57,5.16 28.57,6 28.7,6.12 28.88,6.12 28.98,6.02 28.98,5.16 29.08,5.06 29.28,5.06 29.38,5.16 29.38,6 29.51,6.12 29.69,6.12 29.79,6.02 29.79,5.16 29.89,5.06 30.1,5.06 30.2,5.16 30.2,6 30.32,6.12 30.5,6.12 30.6,6.02 30.6,5.16 30.71,5.06 30.91,5.06 31.01,5.16 31.01,6 31.14,6.12 v2(36.91,6.12)
  BOTTOM w0.127: U11.5 38.38,6.55 38.23,6.4 38.23,5.87 38.13,5.77 37.85,5.77 37.77,5.84 37.77,6.33 37.67,6.43 37.06,6.43 36.91,6.28 v2(36.91,6.12) ; R114.1 26.41,10.74 26.04,10.36 26.04,9.5 26.54,8.99 26.54,7.42 v2(27.58,6.38)
QF_D1_A: length 27.8
  LYR03 w0.127: v2(31.6,5.72) 31.62,5.74 36.73,5.74 36.74,5.73 42.41,5.73 43.28,6.61 v2(43.28,6.68)
  BOTTOM w0.127: v2(31.6,5.72) 27.58,5.72 26.29,7.01 26.29,8.92 25.81,9.41 25.81,11.05 R116.1 ; v2(43.28,6.68) 43.36,6.76 43.36,7.19 45.26,9.09 U11.2
QF_D2_A: length 25.8
  TOP w0.102: R23.2 45.03,7.47 v2(45.36,7.8)
  LYR03 w0.127: v2(45.36,7.8) 45.36,8.28 45.09,8.56 42.7,8.56 42.6,8.46 42.6,8.21 42.7,8.1 44.04,8.1 44.17,7.98 44.17,7.72 44.07,7.62 42.62,7.62 42.55,7.55 42.55,7.24 42.65,7.14 43.56,7.14 43.81,6.88 43.81,5.72 43.41,5.31 32.46,5.31 v2(32.44,5.34)
  BOTTOM w0.127: R106.1 v2(32.44,5.34) ; U11.3 45.67,7.82 45.64,7.8 v2(45.36,7.8)
QF_D3_A: length 26
  LYR03 w0.127: v2(36.91,6.94) 36.8,6.94 36.7,6.83 36.7,6.5 36.6,6.4 36.35,6.4 36.25,6.5 36.25,6.76 36.18,6.82 35.93,6.82 35.86,6.76 35.86,6.5 35.76,6.4 35.52,6.4 35.42,6.5 35.42,6.73 35.33,6.82 35.1,6.82 35.01,6.73 35.01,6.5 34.91,6.4 34.7,6.4 34.6,6.5 34.6,6.73 34.51,6.82 34.29,6.82 34.2,6.73 34.2,6.5 34.07,6.38 32.66,6.38 32.51,6.53 32.51,7.19 32.44,7.27 32.16,7.27 32.08,7.19 32.08,6.5 31.98,6.4 30.18,6.4 30.07,6.5 30.07,7.44 29.97,7.55 29.64,7.55 29.54,7.44 29.54,6.53 29.41,6.4 28.35,6.4 v2(27.58,7.16)
  BOTTOM w0.127: U11.7 37.9,9.09 R95.2 37.44,7.7 36.96,7.22 36.96,6.99 v2(36.91,6.94) ; R115.1 26.41,9.48 26.62,9.27 27.46,9.27 27.56,9.17 27.56,8.94 27.48,8.87 26.9,8.87 26.8,8.76 26.8,8.56 26.9,8.46 27.49,8.46 27.6,8.36 27.6,8.17 27.53,8.1 26.85,8.1 26.8,8.05 26.8,7.8 26.87,7.72 27.46,7.72 27.58,7.6 v2(27.58,7.16)
QF_SS0: length 27.8
  LYR03 w0.127: v2(43.38,9.83) 42.49,9.83 41.56,8.9 41.56,8.77 42.21,8.12 42.21,7.97 42.05,7.81 41.9,7.81 41.25,8.46 41.12,8.46 40.94,8.29 40.94,8.16 41.71,7.39 41.71,7.25 41.57,7.1 41.43,7.1 40.67,7.86 40.52,7.86 39.97,7.32 39.52,7.32 39.37,7.16 39.37,6.28 39.27,6.17 39.07,6.17 38.96,6.28 38.96,7.24 38.86,7.34 38.66,7.34 38.56,7.24 38.56,6.28 38.45,6.17 38.25,6.17 38.15,6.28 38.15,7.19 38,7.34 36.53,7.34 36.23,7.05 34.1,7.05 v1(33.78,6.73)
  BOTTOM w0.127: U11.1 44.07,10.36 43.54,9.83 v2(43.38,9.83) ; v1(33.78,6.73) 33.78,6.78 33.76,6.81 33.76,11.48 R104.2
SAI1_MCLK: length 38.4
  TOP w0.127: U8.M13 44.27,17.77 44.81,17.77 45.16,17.42 46.08,17.42 46.08,17.42 v2(46.03,17.42)
  BOTTOM w0.127: v2(46.03,17.42) 46.22,17.22 46.96,17.22 47.16,17.42 48.37,17.42 48.51,17.27 48.51,16 49.78,14.73 49.78,10.59 47.8,8.61 45.19,8.61 43.69,7.11 43.69,6.47 41.51,4.29 34.34,4.29 33.71,3.66 29.09,3.66 J4.9
SAI1_RX_BCLK: length 38.6
  TOP w0.127: U8.J13 44.28,19.71 45.11,19.71 v2(45.31,19.51)
  BOTTOM w0.127: J4.11 32.98,2.22 34.54,3.79 41.94,3.79 45.47,7.32 48.78,7.32 50.72,9.26 50.72,16.59 49.02,18.29 47.19,18.29 46.93,18.03 46.07,18.03 45.54,17.5 45.26,17.5 44.98,17.78 44.98,19.18 v2(45.31,19.51)
SAI1_RX_SYNC: length 36.8
  TOP w0.127: v2(46.74,17.63) 46.74,17.65 46.58,17.81 46.15,17.81 45.54,18.42 44.27,18.42 U8.L13
  BOTTOM w0.127: v2(46.74,17.63) 46.86,17.76 48.49,17.76 48.84,17.4 48.84,16.13 50.12,14.85 50.12,10.5 47.98,8.35 45.33,8.35 43.95,6.97 43.95,6.24 41.76,4.04 34.42,4.04 33.73,3.35 31.32,3.35 J4.10
SAI1_RXD/AD1_Y-: length 57.2
  TOP w0.127: U8.H12 v1(43.62,21.02) ; v2(58.52,17.93) 58.85,18.26 58.85,24.33 60.23,25.71 J5.37
  LYR03 w0.102: v1(43.62,21.02) 43.84,20.8 46.09,20.8
  LYR03 w0.127: 46.09,20.8 46.42,20.8 46.66,21.03 46.66,21.26 46.94,21.54 47.78,21.54 49.03,20.29 49.03,19.43 49.87,18.58 51.02,18.58 v2(51.05,18.54) 51.05,18.19 51.44,17.81 58.39,17.81 v2(58.52,17.93)
  BOTTOM w0.127: J4.12 35.27,2.99 35.81,3.53 42.01,3.53 45.54,7.06 48.85,7.06 51,9.21 51,18.49 v2(51.05,18.54)
SAI1_TX_BCLK/AD3_X-: length 50.7
  TOP w0.127: J5.35 60.47,24.71 59.51,23.75 59.51,19.69 59.89,19.31 v2(59.89,18.92) ; U8.G12 v1(43.62,21.67)
  LYR03 w0.102: 46.09,21.82 43.78,21.82 v1(43.62,21.67)
  LYR03 w0.127: v2(59.89,18.92) 52.12,18.92 v2(51.82,18.62) 51.82,18.7 51.55,18.96 50,18.96 49.28,19.68 49.28,20.4 49.17,20.5 49.17,20.55 47.9,21.82 46.09,21.82
  BOTTOM w0.127: v2(51.82,18.62) 51.84,18.59 51.84,9.32 51.66,9.14 51.66,9.1 48.25,5.69 48.22,5.69 48.17,5.64 44.81,5.64 41.38,2.22 J4.14
SAI1_TX_SYNC/AD4_X+: length 49.7
  TOP w0.102: U8.J14 45.49,20.04 46.23,19.31
  TOP w0.127: v2(61.02,18.94) 59.84,20.12 59.84,23.37 60.68,24.21 J5.34 ; 46.23,19.31 46.42,19.12 46.8,19.12 46.99,19.31 46.99,19.48 46.99,19.48 46.99,20.09 46.99,20.1 46.99,20.11 47.2,20.32 51.46,20.32 51.51,20.27 v2(51.51,20.31)
  LYR03 w0.127: v2(51.51,20.31) 52.33,19.48 60.48,19.48 v2(61.02,18.94)
  BOTTOM w0.127: v2(51.51,20.31) 51.51,19.56 52.21,18.86 52.21,18.12 52.15,18.06 52.15,9.21 48.34,5.41 46.46,5.41 43.26,2.22 J4.15
SAI1_TXD/AD2_Y+: length 54.8
  TOP w0.127: v2(60.48,17.5) 59.21,18.77 59.21,24.08 60.34,25.21 J5.36 ; U8.H11 v1(42.97,21.02)
  LYR03 w0.102: 46.09,20.54 45.98,20.54 43.89,20.54 43.44,20.54 42.97,21.01 v1(42.97,21.02)
  LYR03 w0.127: v2(60.48,17.5) 60,17.02 52.3,17.02 51.51,16.23 v2(51.44,16.23) 51.44,16.36 47.25,20.54 46.09,20.54
  BOTTOM w0.127: v2(51.44,16.23) 51.44,9.2 48.16,5.92 44.75,5.92 42.32,3.48 42.32,3.47 42.09,3.25 38.71,3.25 37.81,2.35 J4.13
SD1_CLK: length 69.6
  TOP w0.127: U8.J3 v1(37.12,19.72) ; v2(27.57,15.76) 27.64,15.7 27.64,14.58 26.06,13.01 26.06,12.27 24.99,11.2 24.99,6.17 22.99,4.17 v2(22.99,3.68)
  LYR03 w0.127: v2(22.99,3.68) 24.15,4.85 26.99,4.85 27.51,4.33 45.78,4.33 45.79,4.34 45.82,4.34 46.58,5.11 46.58,8.31 48.06,9.78 53.95,9.78 55.42,11.25 58.22,11.25 58.95,10.52 v2(58.95,9.63)
  BOTTOM w0.102: v1(37.12,19.72) 37.09,19.75 35.26,19.75 34.75,19.23 34.28,19.23
  BOTTOM w0.127: v2(58.95,9.63) 58.93,9.65 C116.1 58.94,10.15 R63.1 ; 34.28,19.23 31.04,19.23 v2(27.57,15.76)
SD1_CMD: length 95.6
  TOP w0.127: v2(27.1,15.19) 27.1,14.56 25.68,13.13 25.68,12.37 24.74,11.43 24.74,6.35 22.3,3.91 v2(22.3,3.68) ; U8.J4 v1(37.77,19.72)
  LYR03 w0.127: v2(54.81,11.58) 53.34,10.11 48.03,10.11 46.33,8.41 46.33,5.21 45.68,4.56 27.67,4.56 27.13,5.11 23.52,5.11 22.3,3.89 v2(22.3,3.68)
  BOTTOM w0.102: v1(37.77,19.72) 37.45,19.39 36.92,19.39 36.8,19.52 35.47,19.52 34.8,18.85 34.28,18.85
  BOTTOM w0.127: v2(54.81,11.58) 54.99,11.76 54.99,28.63 54.28,29.34 54.28,30.51 55.73,31.95 55.73,32.31 56.26,32.84 58.8,32.84 59.89,33.94 62.73,33.94 63.46,33.21 R56.1 ; v2(27.1,15.19) 27.64,15.19 31.29,18.85 34.28,18.85
SD1_D0: length 62.9
  TOP w0.127: v2(24.51,3.68) 24.51,4.09 26.54,6.12 26.54,12.52 28.32,14.3 28.32,16.16 31.8,19.64 35.37,19.64 35.77,20.04 U8.J1
  LYR03 w0.127: v2(24.51,3.68) 25.2,4.37 26.75,4.37 27.28,3.84 46.08,3.84 47.09,4.85 47.09,8.13 48.03,9.07 55.04,9.07 56.16,10.19 57.35,10.19 v2(57.96,10.8)
  BOTTOM w0.127: R66.1 58.17,11 v2(57.96,10.8)
SD1_D1: length 59.4
  TOP w0.127: v2(26.42,3.66) 26.42,4.98 27.1,5.67 27.1,12.14 28.85,13.9 28.85,15.83 32.03,19 35.76,19 U8.K1
  LYR03 w0.127: v2(26.42,3.66) 26.77,3.3 46.35,3.3 47.65,4.6 47.65,7.98 48.1,8.43 56.03,8.43 56.58,8.98 56.58,9.67 v2(56.49,9.76)
  BOTTOM w0.127: v2(56.49,9.76) 56.63,9.76 57.26,10.38 R69.1
SD1_D2: length 89.2
  TOP w0.127: v2(23.7,3.68) 23.7,3.74 26.29,6.33 26.29,12.73 28.07,14.5 28.07,16.33 31.67,19.94 31.7,19.94 31.76,20 35.34,20 35.71,20.37 36.48,20.37 U8.H2
  LYR03 w0.127: v2(23.7,3.68) 24.64,4.62 26.9,4.62 27.46,4.07 45.98,4.07 46.84,4.92 46.84,8.23 48.03,9.42 54.33,9.42 55.55,10.64 v2(55.55,10.63)
  BOTTOM w0.127: R60.1 59.83,33.21 58.98,32.36 56.64,32.36 56.21,31.93 56.21,31.32 56.95,30.58 56.95,27.64 55.45,26.14 55.45,10.73 v2(55.55,10.63)
SD1_D3: length 90.8
  TOP w0.127: U8.J2 36.47,19.72 35.84,19.72 35.43,19.31 31.9,19.31 28.6,16 28.6,14.12 26.82,12.35 26.82,5.87 25.6,4.65 v2(25.6,3.68)
  LYR03 w0.127: v2(25.6,3.68) 25.6,3.74 25.95,4.09 26.59,4.09 27.13,3.56 46.13,3.56 47.24,4.68 47.24,4.68 47.37,4.81 47.37,8.03 48.08,8.74 55.73,8.74 v2(56.18,9.2)
  BOTTOM w0.127: v2(56.18,9.2) 55.09,10.29 55.09,11.2 55.22,11.33 55.22,26.39 56.72,27.89 56.72,30.48 55.96,31.24 55.96,32.13 56.41,32.59 58.88,32.59 59.97,33.68 62.51,33.68 62.74,33.45 R58.1
SD_CD: length 6.5
  TOP w0.127: R37.2 D4.1 R38.2 51.36,25.96 v2(51.38,25.93)
  BOTTOM w0.127: J7.10 52.44,28.52 51.38,27.46 v2(51.38,25.93)
SD_CD_SW: length 7.2
  TOP w0.102: U8.D13 44.26,23.6 45.14,23.6 46.02,24.49 46.02,25.15 46.09,25.21
  TOP w0.127: 46.09,25.21 46.66,25.78 49.02,25.78 49.2,25.96 R38.1
SD_CLK: length 27.7
  BOTTOM w0.127: R63.2 R62.2 C44.1 D10.1 60.46,13.94 60.26,14.14 59.8,14.14 59.72,14.23 59.72,14.61 60.15,15.04 61.1,15.04 61.22,14.91 61.22,11.1 61.35,10.97 61.53,10.97 61.68,11.13 61.68,14.81 61.81,14.94 62.06,14.94 62.19,14.81 62.19,11.1 62.32,10.97 62.55,10.97 62.67,11.1 62.67,11.6 62.8,11.73 63.12,11.73 63.25,11.85 63.25,12.11 63.12,12.23 62.8,12.23 62.67,12.36 62.67,12.61 62.8,12.74 63.12,12.74 63.25,12.87 63.25,13.12 63.12,13.25 62.8,13.25 62.67,13.38 62.67,13.82 62.8,13.95 63.68,13.95 64.19,14.45 65.07,14.45 65.29,14.67 J7.5
SD_CMD: length 3.4
  BOTTOM w0.127: R56.2 R57.2 D7.1 64.59,31.42 J7.3
SD_DAT0: length 33.4
  BOTTOM w0.127: J7.7 63.89,14.71 63.7,14.53 62.81,14.53 62.69,14.66 62.69,15.01 62.47,15.23 61.59,15.23 61.47,15.36 61.47,15.61 61.59,15.74 62.59,15.74 62.71,15.86 62.71,16.33 62.59,16.46 60.68,16.46 60.55,16.58 60.55,16.84 60.68,16.96 62.59,16.96 62.71,17.09 62.71,17.34 62.59,17.47 61.06,17.47 60.93,17.6 60.93,17.85 61.06,17.98 62.59,17.98 62.71,18.11 62.71,19.08 62.36,19.43 59.18,19.43 58.93,19.18 58.93,18.58 59.06,18.46 60.02,18.46 60.15,18.33 60.15,18.07 60.02,17.95 59.06,17.95 58.93,17.82 58.93,17.57 59.06,17.44 59.61,17.44 59.74,17.31 59.74,16.98 59.61,16.85 59.06,16.85 58.93,16.73 58.93,16.47 59.06,16.35 59.61,16.35 59.74,16.22 59.74,15.74 59.61,15.61 59.06,15.61 58.93,15.48 58.93,14.72 58.81,14.59 58.37,14.59 58.24,14.47 58.24,14.21 58.37,14.09 58.81,14.09 58.93,13.96 D12.1 R65.2 R66.2
SD_DAT1: length 37.1
  BOTTOM w0.127: R69.2 R68.2 D13.1 56.49,14.12 56.97,14.61 57.89,14.61 58.09,14.81 58.09,15.66 58.22,15.79 58.6,15.79 58.72,15.91 58.72,16.17 58.57,16.32 57.68,16.32 57.56,16.45 57.56,16.7 57.68,16.83 58.6,16.83 58.72,16.95 58.72,17.18 58.57,17.33 57.63,17.33 57.51,17.46 57.51,18.35 57.63,18.48 58.5,18.48 58.62,18.61 58.62,18.81 58.47,18.96 57.58,18.96 57.45,19.09 57.45,19.37 57.58,19.49 58.5,19.49 58.62,19.62 58.62,19.88 58.5,20 57.63,20 57.51,20.13 57.51,20.83 57.66,20.98 58.05,20.98 58.17,21.11 58.17,22.3 58.3,22.43 58.56,22.43 58.68,22.3 58.68,21.06 58.81,20.93 59.06,20.93 59.19,21.06 59.19,22.3 59.32,22.43 59.57,22.43 59.7,22.3 59.7,21.11 59.83,20.98 61.27,20.98 61.4,21.11 61.4,22.2 61.52,22.33 61.78,22.33 61.9,22.2 61.9,21.11 62.03,20.98 62.81,20.98 63.04,20.75 63.04,16.26 63.19,16.11 J7.8
SD_DAT2: length 4.8
  BOTTOM w0.127: J7.1 63.19,30.03 62.76,30.46 61.7,30.46 61.27,30.89 D9.1 R61.2 R60.2
SD_DAT3: length 4.9
  BOTTOM w0.127: J7.2 63.89,30.32 63.4,30.81 62.26,30.81 61.98,31.09 D8.1 R59.2 R58.2
SDRAM_3V3: length 8
  TOP w0.254: U4.C7 v2(17.61,22.36) ; U4.J9 v2(12.01,19.96) ; U4.D3 v2(16.81,25.56) ; U4.B3 v2(18.41,24.76) 18.47,24.7 19.4,24.7 19.6,24.9 ; v2(19.21,21.56) U4.A7 v2(19.21,22.36) ; U4.E7 v2(16.01,21.56)
  TOP w0.305: 19.6,24.9 19.91,25.2 C13.1 ; U4.A9 19.25,19.92 19.25,19.92
  BOTTOM w0.305: v2(16.01,21.56) 15.99,21.58 C98.1
SDRAM_CLK: length 31.8
  TOP w0.127: 35.28,27.76 34.66,28.38 24.37,28.38 24.12,28.13 22.97,28.13 22.85,28.25 22.85,28.51 22.73,28.64 22.27,28.64 22.15,28.51 22.15,27.87 22.02,27.75 21.77,27.75 21.64,27.87 21.64,28.25 21.51,28.38 21.18,28.38 21.05,28.25 21.05,27.87 20.93,27.75 20.67,27.75 20.55,27.87 20.55,28.25 20.42,28.38 20.2,28.38 20.07,28.25 20.07,27.84 19.95,27.71 19.69,27.71 19.57,27.84 19.57,28.25 19.44,28.38 19.18,28.38 19.06,28.25 19.06,27.81 18.93,27.69 18.68,27.69 18.55,27.81 18.55,28.25 18.42,28.38 18.17,28.38 18.04,28.25 18.04,27.79 17.91,27.66 17.66,27.66 17.53,27.79 17.53,28.25 17.41,28.38 17.12,28.38 16.99,28.25 16.99,27.75 16.86,27.62 16.61,27.62 16.48,27.75 16.48,28.25 16.35,28.38 16.1,28.38 15.97,28.25 15.97,27.75 15.85,27.62 15.59,27.62 15.47,27.75 15.47,28.25 15.34,28.38 14.97,28.38 14.43,27.84 14.43,26.34 U4.F2
SEMC_A0: length 34.4
  TOP w0.127: U8.C2 36.48,24.26 35.17,24.26 34.09,25.33 27.07,25.33 26.92,25.19 26.92,24.47 26.77,24.32 26.56,24.32 26.41,24.47 26.41,25.19 26.27,25.33 26.06,25.33 25.91,25.19 25.91,24.47 25.76,24.32 25.55,24.32 25.4,24.47 25.4,25.19 25.25,25.33 25.04,25.33 24.89,25.19 24.89,24.47 24.74,24.32 24.53,24.32 24.38,24.47 24.38,25.19 24.23,25.33 24.02,25.33 23.87,25.19 23.87,24.47 23.73,24.32 23.52,24.32 23.37,24.47 23.37,25.19 23.22,25.33 22.97,25.33 22.85,25.21 22.85,23.81 22.21,23.17 12.94,23.17 12.69,22.92 12.69,22.48 U4.H7
SEMC_A1: length 34.6
  TOP w0.127: U4.H8 12.81,20.76 12.81,19.79 12.69,19.66 12.48,19.66 12.36,19.54 12.36,19.28 12.48,19.16 12.69,19.16 12.81,19.03 12.81,18.53 12.03,17.74 12.03,17.33 13.01,16.35 13.19,16.35 13.46,16.61 13.63,16.61 13.81,16.43 13.81,16.25 13.55,15.99 13.55,15.81 13.73,15.63 13.91,15.63 14.17,15.9 14.35,15.9 14.53,15.72 14.53,15.54 14.27,15.27 14.27,15.09 14.44,14.92 24.35,14.92 30.51,21.08 34.75,21.08 35.01,21.34 U8.G1
SEMC_A2: length 34.7
  TOP w0.127: U4.J8 11.6,20.34 11.6,19.11 11.72,18.98 11.93,18.98 12.05,18.85 12.05,18.6 11.93,18.47 11.72,18.47 11.6,18.35 11.6,17.13 14.19,14.54 24.45,14.54 30.61,20.7 34.97,20.7 35.29,21.02 37.12,21.02 U8.G3
SEMC_A3: length 34.3
  TOP w0.127: U4.J7 11.27,20.81 11.27,16.85 13.96,14.16 24.58,14.16 30.73,20.32 35.16,20.32 35.54,20.69 U8.H1
SEMC_A4: length 36.7
  TOP w0.127: U4.J3 11.29,26.27 11.29,28.38 14.47,31.56 34.79,31.56 39.07,27.28 39.07,25.93 39.4,25.6 U8.A6
SEMC_A5: length 35.4
  TOP w0.127: U8.B6 39.08,24.91 39.08,25.44 38.76,25.76 38.76,27.11 34.7,31.18 14.59,31.18 11.62,28.2 11.62,26.74 U4.J2
SEMC_A6: length 34.8
  TOP w0.127: U4.H3 12.43,24.38 12.43,23.81 12.69,23.56 13.04,23.56 13.18,23.7 13.18,24.17 13.33,24.32 13.54,24.32 13.69,24.17 13.69,23.7 13.84,23.56 21.45,23.56 22.47,24.57 22.47,25.46 22.72,25.71 29.7,25.71 29.85,25.86 29.85,26.33 29.99,26.48 30.2,26.48 30.35,26.33 30.35,25.86 30.5,25.71 30.71,25.71 30.86,25.86 30.86,26.33 31.01,26.48 31.22,26.48 31.37,26.33 31.37,25.86 31.52,25.71 31.73,25.71 31.88,25.86 31.88,26.33 32.03,26.48 32.24,26.48 32.39,26.33 32.39,25.86 32.53,25.71 32.74,25.71 32.89,25.86 32.89,26.33 33.04,26.48 33.25,26.48 33.4,26.33 33.4,25.86 33.55,25.71 33.76,25.71 33.91,25.86 33.91,26.33 34.06,26.48 34.27,26.48 34.42,26.33 34.42,25.86 34.57,25.71 34.79,25.71 34.91,25.59 34.91,24.95 35.27,24.59 U8.B1
SEMC_A7: length 35
  TOP w0.102: 38.45,26.35 38.45,25.54 U8.A5
  TOP w0.127: 38.45,26.35 38.45,26.89 34.54,30.79 31.77,30.79 31.62,30.65 31.62,30.56 31.47,30.41 31.26,30.41 31.11,30.56 31.11,30.65 30.96,30.79 30.75,30.79 30.61,30.65 30.61,30.56 30.46,30.41 30.25,30.41 30.1,30.56 30.1,30.65 29.95,30.79 29.74,30.79 29.59,30.65 29.59,30.56 29.44,30.41 29.23,30.41 29.08,30.56 29.08,30.65 28.93,30.79 28.72,30.79 28.57,30.65 28.57,30.56 28.42,30.41 28.21,30.41 28.07,30.56 28.07,30.65 27.92,30.79 27.71,30.79 27.56,30.65 27.56,30.56 27.41,30.41 27.2,30.41 27.05,30.56 27.05,30.65 26.9,30.79 14.72,30.79 12.81,28.89 12.81,26.35 U4.H2
SEMC_A8: length 34.8
  TOP w0.127: U8.A4 38.1,26.73 34.8,30.03 26.31,30.03 26.16,30.18 26.16,30.27 26.01,30.41 25.8,30.41 25.65,30.27 25.65,30.18 25.5,30.03 25.29,30.03 25.15,30.18 25.15,30.27 25,30.41 24.79,30.41 24.64,30.27 24.64,30.18 24.49,30.03 24.28,30.03 24.13,30.18 24.13,30.27 23.98,30.41 23.77,30.41 23.62,30.27 23.62,30.18 23.47,30.03 23.26,30.03 23.11,30.18 23.11,30.27 22.96,30.41 22.75,30.41 22.61,30.27 22.61,30.18 22.46,30.03 22.25,30.03 22.1,30.18 22.1,30.27 21.95,30.41 21.74,30.41 21.59,30.27 21.59,30.18 21.44,30.03 21.23,30.03 21.08,30.18 21.08,30.27 20.93,30.41 20.72,30.41 20.57,30.27 20.57,30.18 20.42,30.03 20.21,30.03 20.07,30.18 20.07,30.27 19.92,30.41 19.71,30.41 19.56,30.27 19.56,30.18 19.41,30.03 19.2,30.03 19.05,30.18 19.05,30.27 18.9,30.41 18.69,30.41 18.54,30.27 18.54,30.18 18.39,30.03 18.18,30.03 18.03,30.18 18.03,30.27 17.88,30.41 17.67,30.41 17.53,30.27 17.53,30.18 17.38,30.03 17.17,30.03 17.02,30.18 17.02,30.27 16.87,30.41 16.66,30.41 16.51,30.27 16.51,30.18 16.36,30.03 16.15,30.03 16,30.18 16,30.27 15.85,30.41 15.64,30.41 15.49,30.27 15.49,30.18 15.34,30.03 14.47,30.03 13.21,28.78 U4.H1
SEMC_A9: length 35.3
  TOP w0.127: U4.G3 15.23,23.94 21.32,23.94 22.09,24.7 22.09,26.48 22.47,26.86 22.65,26.86 22.8,26.71 22.8,26.24 22.95,26.1 23.16,26.1 23.31,26.24 23.31,26.71 23.46,26.86 23.67,26.86 23.82,26.71 23.82,26.24 23.97,26.1 24.18,26.1 24.33,26.24 24.33,26.71 24.47,26.86 24.68,26.86 24.83,26.71 24.83,26.24 24.98,26.1 25.19,26.1 25.34,26.24 25.34,26.71 25.49,26.86 25.7,26.86 25.85,26.71 25.85,26.24 26,26.1 26.21,26.1 26.36,26.24 26.36,26.71 26.51,26.86 26.72,26.86 26.87,26.71 26.87,26.24 27.01,26.1 27.22,26.1 27.37,26.24 27.37,26.71 27.52,26.86 27.73,26.86 27.88,26.71 27.88,26.24 28.03,26.1 28.24,26.1 28.39,26.24 28.39,26.71 28.54,26.86 28.75,26.86 28.9,26.71 28.9,26.24 29.05,26.1 29.26,26.1 29.41,26.24 29.41,26.71 29.55,26.86 34.66,26.86 35.29,26.22 35.29,25.16 35.55,24.91 36.29,24.91 36.6,24.59 U8.B2
